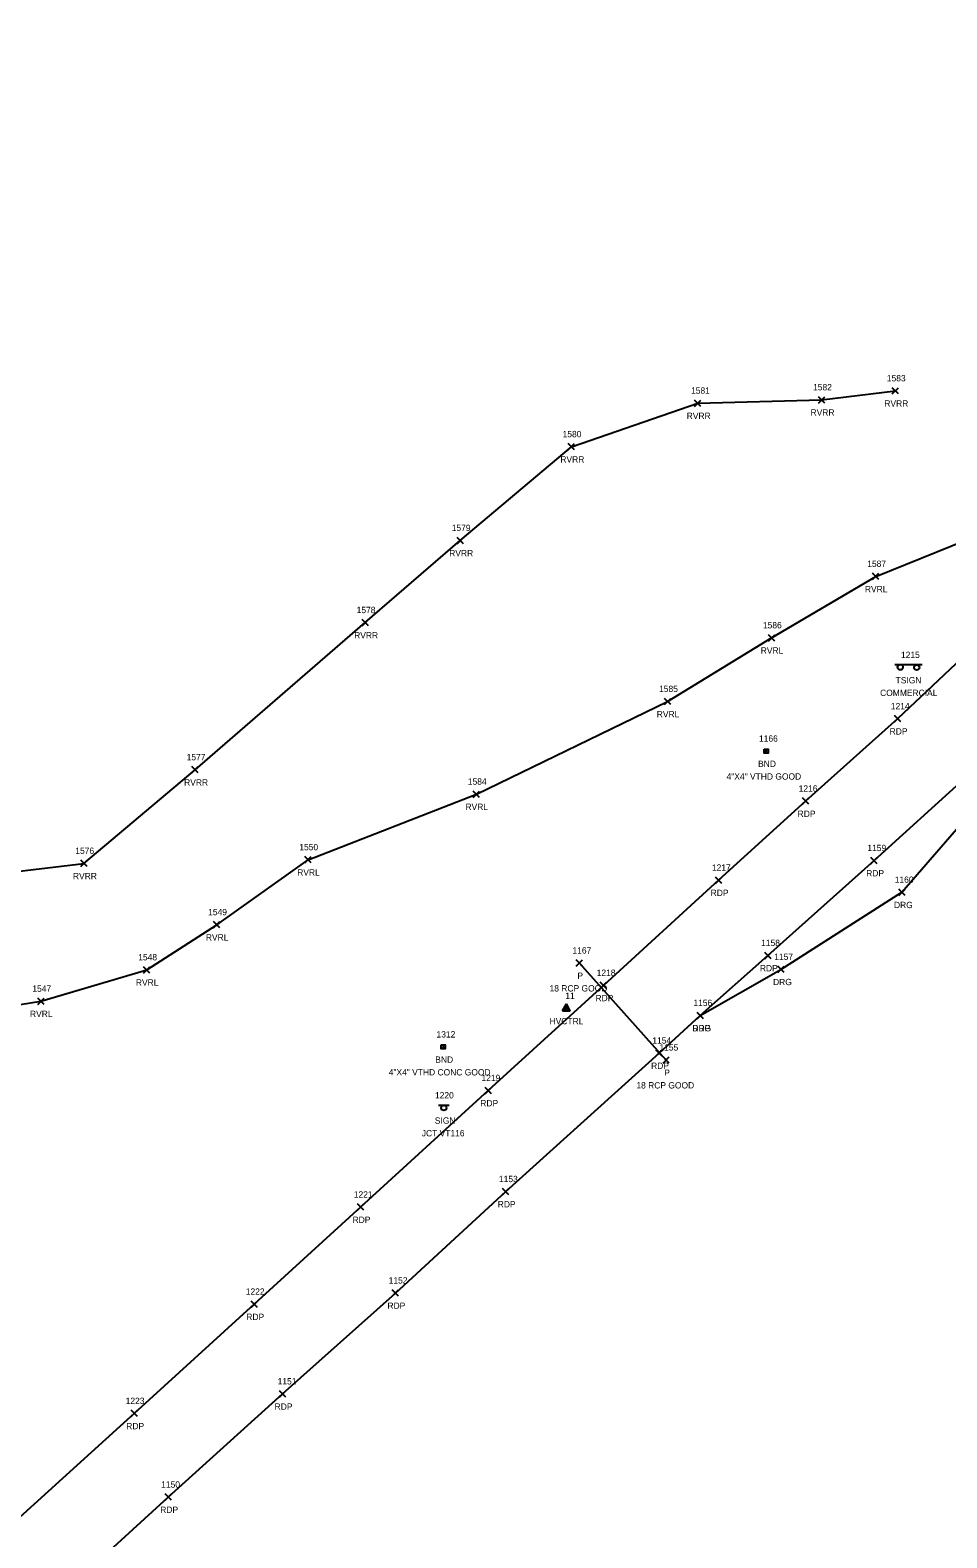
# Model space of a CAD drawing. Extents: x 1496556 to 1498241, y 599216 to 604470.
# Drawn here: x 1497547.4 to 1497837.4, y 603254 to 603730.8 of the extents above; entities that cross this region are included whole.
import ezdxf

# ---------------------------------------------------------------- set-up
doc = ezdxf.new("R2010")
doc.units = 0
for name, color, linetype in [('C_A', 7, 'Continuous'), ('C_I', 7, 'Continuous'), ('CPSM', 7, 'Continuous'), ('D_A', 7, 'Continuous'), ('D_C', 7, 'Continuous'), ('D_I', 7, 'Continuous'), ('D_TIC', 7, 'Continuous'), ('DCP', 7, 'Continuous'), ('L_A', 7, 'Continuous'), ('L_I', 7, 'Continuous'), ('L_TIC', 7, 'Continuous'), ('LAWE', 7, 'Continuous'), ('Level 18', 7, 'Continuous'), ('M_A', 7, 'Continuous'), ('M_C', 7, 'Continuous'), ('M_I', 7, 'Continuous'), ('P_A', 7, 'Continuous'), ('P_I', 7, 'Continuous'), ('P_TIC', 7, 'Continuous'), ('PET', 7, 'Continuous'), ('R_A', 7, 'Continuous'), ('R_I', 7, 'Continuous'), ('R_TIC', 7, 'Continuous'), ('RDG', 7, 'Continuous'), ('S_A', 7, 'Continuous'), ('S_C', 7, 'Continuous'), ('S_I', 7, 'Continuous'), ('SSGN', 7, 'Continuous')]:
    doc.layers.add(name, color=color, linetype=linetype)

msp = doc.modelspace()

# ---------------------------------------------------------------- linework, layer by layer
at = {"layer": 'CPSM'}
for p, q in [((1497715.78, 603420.72), (1497717.03, 603422.89)), ((1497715.78, 603420.72), (1497717.03, 603421.44)), ((1497715.78, 603420.72), (1497718.28, 603420.72)), ((1497718.28, 603420.72), (1497717.03, 603422.89)), ((1497717.03, 603421.44), (1497717.03, 603422.89)), ((1497717.03, 603421.44), (1497717.03, 603421.44)), ((1497717.03, 603421.44), (1497718.28, 603420.72))]:
    msp.add_line(p, q, dxfattribs=at)
at = {"layer": 'D_TIC'}
for points in [[(1497720.15, 603434.8), (1497722.15, 603436.8)], [(1497722.15, 603434.8), (1497720.15, 603436.8)], [(1497747.6, 603404.13), (1497749.6, 603406.13)], [(1497749.6, 603404.13), (1497747.6, 603406.13)]]:
    msp.add_lwpolyline(points, dxfattribs=at)
at = {"layer": 'DCP'}
msp.add_lwpolyline([(1497748.6, 603405.13), (1497721.15, 603435.8)], dxfattribs=at)
at = {"layer": 'L_TIC'}
for points in [[(1497796.76, 603612.89), (1497798.76, 603614.89)], [(1497798.76, 603612.89), (1497796.76, 603614.89)], [(1497820.1, 603615.74), (1497822.1, 603617.74)], [(1497822.1, 603615.74), (1497820.1, 603617.74)], [(1497757.59, 603611.82), (1497759.59, 603613.82)], [(1497759.59, 603611.82), (1497757.59, 603613.82)], [(1497717.62, 603598.07), (1497719.62, 603600.07)], [(1497719.62, 603598.07), (1497717.62, 603600.07)], [(1497682.47, 603568.4), (1497684.47, 603570.4)], [(1497684.47, 603568.4), (1497682.47, 603570.4)], [(1497813.89, 603557.06), (1497815.89, 603559.06)], [(1497815.89, 603557.06), (1497813.89, 603559.06)], [(1497652.4, 603542.44), (1497654.4, 603544.44)], [(1497654.4, 603542.44), (1497652.4, 603544.44)], [(1497780.95, 603537.62), (1497782.95, 603539.62)], [(1497782.95, 603537.62), (1497780.95, 603539.62)], [(1497748.06, 603517.5), (1497750.06, 603519.5)], [(1497750.06, 603517.5), (1497748.06, 603519.5)], [(1497598.61, 603495.91), (1497600.61, 603497.91)], [(1497600.61, 603495.91), (1497598.61, 603497.91)], [(1497687.56, 603488.19), (1497689.56, 603490.19)], [(1497689.56, 603488.19), (1497687.56, 603490.19)], [(1497563.45, 603466.31), (1497565.45, 603468.31)], [(1497565.45, 603466.31), (1497563.45, 603468.31)], [(1497634.34, 603467.46), (1497636.34, 603469.46)], [(1497636.34, 603467.46), (1497634.34, 603469.46)], [(1497605.43, 603446.91), (1497607.43, 603448.91)], [(1497607.43, 603446.91), (1497605.43, 603448.91)], [(1497583.3, 603432.63), (1497585.3, 603434.63)], [(1497585.3, 603432.63), (1497583.3, 603434.63)], [(1497549.81, 603422.71), (1497551.81, 603424.71)], [(1497551.81, 603422.71), (1497549.81, 603424.71)]]:
    msp.add_lwpolyline(points, dxfattribs=at)
at = {"layer": 'LAWE'}
for points in [[(1497519.31, 603418.69), (1497550.81, 603423.71), (1497584.3, 603433.63), (1497606.43, 603447.91), (1497635.34, 603468.46), (1497688.56, 603489.19), (1497749.06, 603518.5), (1497781.95, 603538.62), (1497814.89, 603558.06), (1497852.95, 603573.46), (1497879.04, 603589.04), (1497900.98, 603619.87)], [(1497518.38, 603461.84), (1497564.45, 603467.31), (1497599.61, 603496.91), (1497653.4, 603543.44), (1497683.47, 603569.4), (1497718.62, 603599.07), (1497758.59, 603612.82), (1497797.76, 603613.89), (1497821.1, 603616.74)]]:
    msp.add_lwpolyline(points, dxfattribs=at)
at = {"layer": 'Level 18'}
for points in [[(1497779.56, 603503.42), (1497780.81, 603503.42), (1497780.81, 603502.17), (1497779.56, 603502.17)], [(1497677.46, 603409.88), (1497678.71, 603409.88), (1497678.71, 603408.63), (1497677.46, 603408.63)]]:
    msp.add_lwpolyline(points, close=True, dxfattribs=at)
for centre in [(1497780.19, 603502.79), (1497678.08, 603409.25)]:
    msp.add_circle(centre, 0.0833, dxfattribs=at)
at = {"layer": 'P_TIC'}
for points in [[(1497820.8, 603512.04), (1497822.8, 603514.04)], [(1497822.8, 603512.04), (1497820.8, 603514.04)], [(1497791.69, 603485.99), (1497793.69, 603487.99)], [(1497793.69, 603485.99), (1497791.69, 603487.99)], [(1497813.38, 603467.18), (1497815.38, 603469.18)], [(1497815.38, 603467.18), (1497813.38, 603469.18)], [(1497764.2, 603460.99), (1497766.2, 603462.99)], [(1497766.2, 603460.99), (1497764.2, 603462.99)], [(1497779.77, 603437.17), (1497781.77, 603439.17)], [(1497781.77, 603437.17), (1497779.77, 603439.17)], [(1497727.75, 603427.73), (1497729.75, 603429.73)], [(1497729.75, 603427.73), (1497727.75, 603429.73)], [(1497758.4, 603418.2), (1497760.4, 603420.2)], [(1497760.4, 603418.2), (1497758.4, 603420.2)], [(1497745.34, 603406.32), (1497747.34, 603408.32)], [(1497747.34, 603406.32), (1497745.34, 603408.32)], [(1497691.32, 603394.47), (1497693.32, 603396.47)], [(1497693.32, 603394.47), (1497691.32, 603396.47)], [(1497696.84, 603362.51), (1497698.84, 603364.51)], [(1497698.84, 603362.51), (1497696.84, 603364.51)], [(1497650.92, 603357.61), (1497652.92, 603359.61)], [(1497652.92, 603357.61), (1497650.92, 603359.61)], [(1497617.31, 603326.9), (1497619.31, 603328.9)], [(1497619.31, 603326.9), (1497617.31, 603328.9)], [(1497661.95, 603330.45), (1497663.95, 603332.45)], [(1497663.95, 603330.45), (1497661.95, 603332.45)], [(1497626.26, 603298.53), (1497628.26, 603300.53)], [(1497628.26, 603298.53), (1497626.26, 603300.53)], [(1497579.33, 603292.36), (1497581.33, 603294.36)], [(1497581.33, 603292.36), (1497579.33, 603294.36)], [(1497590.08, 603265.91), (1497592.08, 603267.91)], [(1497592.08, 603265.91), (1497590.08, 603267.91)]]:
    msp.add_lwpolyline(points, dxfattribs=at)
at = {"layer": 'PET'}
for points in [[(1497522.29, 603204.31), (1497552.95, 603231.97), (1497591.08, 603266.91), (1497627.26, 603299.53), (1497662.95, 603331.45), (1497697.84, 603363.51), (1497746.34, 603407.32), (1497759.4, 603419.2), (1497780.77, 603438.17), (1497814.38, 603468.18), (1497842.75, 603493.95), (1497876.67, 603525.23), (1497903.96, 603551.93), (1497933.62, 603583.71), (1497962.05, 603618.46), (1497981.16, 603645.77), (1498004.55, 603682.86), (1498024.5, 603720), (1498039.75, 603752.79)], [(1498003.54, 603741.59), (1497984.58, 603705.71), (1497962.45, 603669.56), (1497942.61, 603640.73), (1497917.66, 603609.52), (1497887.48, 603576.77), (1497854.98, 603544.28), (1497821.8, 603513.04), (1497792.69, 603486.99), (1497765.2, 603461.99), (1497728.75, 603428.73), (1497692.32, 603395.47), (1497651.92, 603358.61), (1497618.31, 603327.9), (1497580.33, 603293.36), (1497544.07, 603260.5)]]:
    msp.add_lwpolyline(points, dxfattribs=at)
at = {"layer": 'R_TIC'}
for points in [[(1497822.17, 603457.16), (1497824.17, 603459.16)], [(1497824.17, 603457.16), (1497822.17, 603459.16)], [(1497783.91, 603432.8), (1497785.91, 603434.8)], [(1497785.91, 603432.8), (1497783.91, 603434.8)], [(1497758.4, 603418.2), (1497760.4, 603420.2)], [(1497760.4, 603418.2), (1497758.4, 603420.2)]]:
    msp.add_lwpolyline(points, dxfattribs=at)
at = {"layer": 'RDG'}
msp.add_lwpolyline([(1497759.4, 603419.2), (1497784.91, 603433.8), (1497823.17, 603458.16), (1497849.43, 603488.43), (1497878.7, 603522.75), (1497903.96, 603551.93)], dxfattribs=at)
at = {"layer": 'SSGN'}
for p, q in [((1497820.98, 603530.15), (1497829.58, 603530.15)), ((1497825, 603529.25), (1497825, 603529.25)), ((1497676.63, 603390.84), (1497679.96, 603390.84)), ((1497678.27, 603390), (1497678.27, 603390))]:
    msp.add_line(p, q, dxfattribs=at)
for centre in [(1497822.64, 603529.32), (1497827.85, 603529.25), (1497678.27, 603390)]:
    msp.add_circle(centre, 0.833, dxfattribs=at)

# ---------------------------------------------------------------- texts
at = {"layer": 'C_A'}
msp.add_text('HVCTRL', height=2, dxfattribs=at).set_placement((1497711.72, 603416.44))
at = {"layer": 'C_I'}
msp.add_text('11', height=2, dxfattribs=at).set_placement((1497716.7, 603424.44))
at = {"layer": 'D_A'}
for p in [(1497720.52, 603430.8), (1497747.98, 603400.13)]:
    msp.add_text('P', height=2, dxfattribs=at).set_placement(p)
at = {"layer": 'D_C'}
for p in [(1497711.72, 603426.8), (1497739.18, 603396.13)]:
    msp.add_text('18 RCP GOOD', height=2, dxfattribs=at).set_placement(p)
at = {"layer": 'D_I'}
for s, p in [('1167', (1497718.97, 603438.8)), ('1155', (1497746.48, 603408.13))]:
    msp.add_text(s, height=2, dxfattribs=at).set_placement(p)
at = {"layer": 'L_A'}
for s, p in [('RVRR', (1497755.1, 603607.82)), ('RVRR', (1497794.27, 603608.89)), ('RVRR', (1497817.61, 603611.74)), ('RVRR', (1497715.13, 603594.07)), ('RVRR', (1497679.98, 603564.4)), ('RVRL', (1497811.46, 603553.06)), ('RVRR', (1497649.91, 603538.44)), ('RVRL', (1497778.52, 603533.62)), ('RVRL', (1497745.62, 603513.5)), ('RVRR', (1497596.13, 603491.91)), ('RVRL', (1497685.12, 603484.19)), ('RVRR', (1497560.96, 603462.31)), ('RVRL', (1497631.9, 603463.46)), ('RVRL', (1497603, 603442.91)), ('RVRL', (1497580.87, 603428.63)), ('RVRL', (1497547.38, 603418.71))]:
    msp.add_text(s, height=2, dxfattribs=at).set_placement(p)
at = {"layer": 'L_I'}
for s, p in [('1582', (1497795.07, 603616.89)), ('1583', (1497818.4, 603619.74)), ('1581', (1497756.47, 603615.82)), ('1580', (1497715.84, 603602.07)), ('1579', (1497680.77, 603572.4)), ('1587', (1497812.2, 603561.06)), ('1578', (1497650.7, 603546.44)), ('1586', (1497779.2, 603541.62)), ('1585', (1497746.36, 603521.5)), ('1577', (1497596.92, 603499.91)), ('1584', (1497685.86, 603492.19)), ('1576', (1497561.7, 603470.31)), ('1550', (1497632.56, 603471.46)), ('1549', (1497603.73, 603450.91)), ('1548', (1497581.61, 603436.63)), ('1547', (1497548.12, 603426.71))]:
    msp.add_text(s, height=2, dxfattribs=at).set_placement(p)
at = {"layer": 'M_A'}
for p in [(1497777.68, 603497.79), (1497675.57, 603404.25)]:
    msp.add_text('BND', height=2, dxfattribs=at).set_placement(p)
at = {"layer": 'M_C'}
for s, p in [('4"X4" VTHD GOOD', (1497767.71, 603493.79)), ('4"X4" VTHD CONC GOOD', (1497660.85, 603400.25))]:
    msp.add_text(s, height=2, dxfattribs=at).set_placement(p)
at = {"layer": 'M_I'}
for s, p in [('1166', (1497777.96, 603505.79)), ('1312', (1497675.96, 603412.25))]:
    msp.add_text(s, height=2, dxfattribs=at).set_placement(p)
at = {"layer": 'P_A'}
for p in [(1497819.29, 603508.04), (1497790.18, 603481.99), (1497811.87, 603463.18), (1497762.68, 603456.99), (1497778.25, 603433.17), (1497726.24, 603423.73), (1497756.89, 603414.2), (1497743.83, 603402.32), (1497689.81, 603390.47), (1497695.33, 603358.51), (1497649.4, 603353.61), (1497660.44, 603326.45), (1497615.8, 603322.9), (1497624.75, 603294.53), (1497577.82, 603288.36), (1497588.57, 603261.91)]:
    msp.add_text('RDP', height=2, dxfattribs=at).set_placement(p)
at = {"layer": 'P_I'}
for s, p in [('1214', (1497819.67, 603516.04)), ('1216', (1497790.51, 603489.99)), ('1159', (1497812.24, 603471.18)), ('1217', (1497763.07, 603464.99)), ('1158', (1497778.64, 603441.17)), ('1218', (1497726.62, 603431.73)), ('1156', (1497757.22, 603422.2)), ('1154', (1497744.22, 603410.32)), ('1219', (1497690.19, 603398.47)), ('1153', (1497695.71, 603366.51)), ('1221', (1497649.79, 603361.61)), ('1222', (1497615.62, 603330.9)), ('1152', (1497660.83, 603334.45)), ('1151', (1497625.71, 603302.53)), ('1223', (1497577.64, 603296.36)), ('1150', (1497588.87, 603269.91))]:
    msp.add_text(s, height=2, dxfattribs=at).set_placement(p)
at = {"layer": 'R_A'}
for p in [(1497820.66, 603453.16), (1497782.4, 603428.8), (1497756.89, 603414.2)]:
    msp.add_text('DRG', height=2, dxfattribs=at).set_placement(p)
at = {"layer": 'R_I'}
for s, p in [('1160', (1497820.91, 603461.16)), ('1157', (1497782.78, 603436.8)), ('1156', (1497757.22, 603422.2))]:
    msp.add_text(s, height=2, dxfattribs=at).set_placement(p)
at = {"layer": 'S_A'}
for s, p in [('TSIGN', (1497821.18, 603524.23)), ('SIGN', (1497675.41, 603384.98))]:
    msp.add_text(s, height=2, dxfattribs=at).set_placement(p)
at = {"layer": 'S_C'}
for s, p in [('COMMERCIAL', (1497816.27, 603520.23)), ('JCT VT116', (1497671.3, 603380.98))]:
    msp.add_text(s, height=2, dxfattribs=at).set_placement(p)
at = {"layer": 'S_I'}
for s, p in [('1215', (1497822.87, 603532.23)), ('1220', (1497675.47, 603392.98))]:
    msp.add_text(s, height=2, dxfattribs=at).set_placement(p)

doc.saveas('drawing.dxf')
